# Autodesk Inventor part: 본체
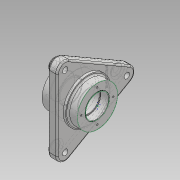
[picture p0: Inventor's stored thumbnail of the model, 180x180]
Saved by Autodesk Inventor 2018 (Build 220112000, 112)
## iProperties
Created: 2023-04
Part Number: 본체
Material: 일반
Document SubType Name: Modeling
Designer: home
Density: 1 g/cm^3
Appearance: 기본값
Author: home
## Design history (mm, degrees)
sketch "스케치1" dims "d0" = 57
  geometry: L1 (-33, 84.87)-(90, 13.856); L2 (90, -13.856)-(-33, -84.87); L3 (-57, -71.014)-(-57, 71.014); A1 r 16 centre (82, 0) between (90, -13.856) and (90, 13.856); A2 r 16 centre (-41, 71.014) between (-33, 84.87) and (-57, 71.014); A3 r 16 centre (-41, -71.014) between (-57, -71.014) and (-33, -84.87); 7 further points
  constraints: 6 end point, 6 point on circle, 6 point on line, 6 tangent, 3 centre point, 2 coincident, 2 equal radius, 1 horizontal alignment, 1 midpoint, 9 other
  dimensions: "d1" = 16 radius of A1 (derived)
extrude "돌출1" new body sketch "스케치1" distance "d2" = 18; taper "d3" = 0 deg
sketch "스케치2"
  geometry: C1 r 45 at (0, 0); 1 further point
  constraints: 1 centre point, 1 coincident
  dimensions: "d4" = 90 diameter of C1
extrude "돌출2" join sketch "스케치2" distance "d5" = 5; taper "d6" = 0 deg
sketch "스케치3"
  geometry: C1 r 45 at (0, 0) reference; C2 r 40 at (0, 0)
  constraints: 1 centre point, 1 coincident
  dimensions: "d7" = 80 diameter of C2
extrude "돌출3" join sketch "스케치3" distance "d8" = 18; taper "d9" = 0 deg
sketch "스케치4"
  geometry: C1 r 40 at (0, 0); 1 further point
  constraints: 1 centre point, 1 coincident
  dimensions: "d10" = 80 diameter of C1
extrude "돌출4" join sketch "스케치4" distance "d11" = 29; taper "d12" = 0 deg
sketch "스케치5"
  geometry: C1 r 40 at (0, 0) reference; 1 further point
  constraints: 1 coincident
hole "구멍1" sketch "스케치5" at (0, 0) diameter "d13" = 42; stored, may be unused: countersink angle "d17" = 90 deg, drill point angle "d19" = 0 deg; dims "d14" = 6, "d15" = 47, "d16" = 17, "d18" = 18
sketch "스케치6"
  geometry: C1 r 40 at (0, 0) reference
hole "구멍2" sketch "스케치6" at (0, 0) diameter "d20" = 42; stored, may be unused: countersink angle "d24" = 90 deg, drill point angle "d26" = 0 deg; dims "d21" = 6, "d22" = 47, "d23" = 17, "d25" = 18
sketch "스케치7"
  geometry: C1 r 23.5 at (0, 0) reference; C2 r 40 at (0, 0) reference; 1 further point
  constraints: 1 coincident
sketch "스케치8"
  geometry: C1 r 40 at (0, 0) reference; C2 r 82 at (0, 0); C3 r 11 at (0, 82); A1 r 16 centre (0, 82) between (13.856, 90) and (-13.856, 90) reference
  constraints: 2 centre point, 2 coincident
  dimensions: "d27" = 164 diameter of C2; "d28" = 22 diameter of C3
extrude "돌출5" join sketch "스케치8" distance "d29" = 4; taper "d30" = 0 deg
sketch "스케치9"
  geometry: C1 r 11 at (0, 0) reference; C2 r 5.5 at (0, 0); 1 further point
  constraints: 1 centre point, 1 coincident
  dimensions: "d31" = 11 diameter of C2
extrude "돌출6" cut sketch "스케치9" extent not by distance; stored distance "d32" = 4; taper "d33" = 0 deg
sketch "스케치10"
  geometry: C1 r 23.5 at (0, 0) reference; 1 further point
  dimensions: "d37" = 32 distance of C1.centre point (0, 32)
hole "구멍3" sketch "스케치10" at (0, 32) diameter "d38" = 3.242; stored, may be unused: countersink angle "d42" = 90 deg, drill point angle "d44" = 118 deg; dims "d39" = 8, "d40" = 4, "d41" = 2, "d43" = 10
sketch "스케치11"
  geometry: C1 r 1.621 at (0, 32) reference; 1 further point
  constraints: 1 coincident
hole "구멍4" sketch "스케치11" at (0, 32) diameter "d48" = 3.242; stored, may be unused: countersink angle "d52" = 90 deg, drill point angle "d54" = 118 deg; dims "d49" = 8, "d50" = 4, "d51" = 2, "d53" = 10
fillet "모깎기1" dims "d58" = 3
fillet "모깎기2" dims "d59" = 3
fillet "모깎기3" dims "d60" = 3
fillet "모깎기4" dims "d61" = 3
chamfer "모따기1" distance "d62" = 1; stored, may be unused: second distance "d63" = 2, angle "d64" = 45 deg
sketch "스케치12"
  geometry: 3 further points
  constraints: 1 horizontal alignment, 2 other
  dimensions: "d65" = 60 vertical distance of point (0, 0) point (0.255, 60)
feature "엠보싱1" sketch "스케치12" dims "d7" = 80, "d66" = 0.5, "d67" = 0
fillet "모깎기5" dims "d68" = 0.6
node "솔리드1"
pattern_circular "원형 패턴1" dims angle "d35" = 360 deg
pattern_circular "원형 패턴2" dims angle "d46" = 360 deg
pattern_circular "원형 패턴3" dims angle "d56" = 360 deg
